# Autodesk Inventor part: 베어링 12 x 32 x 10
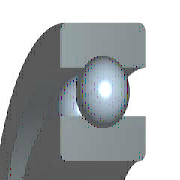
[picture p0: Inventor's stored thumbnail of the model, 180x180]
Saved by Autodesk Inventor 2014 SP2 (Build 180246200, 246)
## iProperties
IsCustomPart: 1
Created: 2012-02
Part Number: 베어링 12 x 32 x 10
Material: 강철, 연강
Description: 깊은 그루브 볼 베어링
Document SubType Name: Modeling
Standard: KS B 2023
Designer: test
Standards Organization: KS
Language: ko-KR
Size Designation: 6201 - 12 x 32 x 10
Categories: <MemberInstance><Categories><Category DisplayName="샤프트 부품" InternalName="7f7aeb1f-a693-4053-b835-cee3144e0d98" Mnemonic="SHFT"><Category DisplayName="베어링" Inter
Density: 1 g/cm^3
Appearance: 강철
Author: test
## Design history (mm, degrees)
sketch "스케치" dims "d0" = 5.2 (= -0.26 x WD + 0.26 x BD)
  geometry: L1 (2.4, 11)-(7.6, 11); L2 (5, 11)-(5, 8.4); L3 (5, 11)-(5, 13.6); L4 (3.068, 9.26)-(0, 9.26); L5 (0, 6)-(10, 6); L6 (3.068, 12.74)-(0, 12.74); L7 (0, 16)-(10, 16); L8 (10, 6)-(10, 9.26); L9 (6.932, 9.26)-(10, 9.26); L10 (6.932, 12.74)-(10, 12.74); L11 (10, 16)-(10, 12.74); L12 (-1.4, 0)-(8.4, 0) reference; L13 (0, -0.3)-(0, 5.3) reference
  constraints: 22 end point, 4 point on line, 2 collinear, 2 perpendicular, 2 symmetric about line, 1 midpoint, 1 parallel, 14 other
  dimensions: "d9" = 12 diameter of L5 L12 (= WD); "d11" = 32 diameter of L7 L12 (= BD); "d12" = 10 distance between parallel lines of L8 L13 (= KB); "d13" = 18.52 diameter of L9 L12 (= 0.326 x BD + 0.674 x WD)
revolve "본체" stored, may be unused: angle "d6" = 90 deg
revolve "볼" stored, may be unused: angle "d7" = 90 deg
pattern_circular "IDS_ARRAYBALL[SIMPL:T]" dims angle "d3" = 360 deg
body "Solid1"
fillet "모깎기1" dims "d1" = 0.6 (= KRS)
other parameters: "WD" = 12 [user parameter; used in 5 equation terms], "BD" = 32 [user parameter; used in 5 equation terms], "KB" = 10 [user parameter; used in 1 equation term], "KRS" = 0.6 [user parameter; used in 1 equation term], "d4" = 0, "d5" = 0, "d8" = 0, "d14" = 0, "d15" = 0, "BBA" = 0 [user parameter], "BC0" = 3100000 [user parameter], "BC" = 6890000 [user parameter], "BR" = 16 (= 0.5 x BD) [user parameter], "WR" = 6 (= 0.5 x WD) [user parameter]
